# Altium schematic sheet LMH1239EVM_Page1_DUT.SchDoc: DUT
size 431 x 279 mm; Date: Not shown in title block; ApprovedBy: Not shown in title block; CheckedBy: Not shown in title block; Author: Not shown in title block; CompanyName: Not shown in title block; Engineer: Texas Instruments; Organization: Not shown in title block; Address1: Not shown in title block; Address2: Not shown in title block; Address3: Not shown in title block; Address4: Not shown in title block; DocumentNumber: 1; Revision: A; SheetNumber: 1; SheetTotal: 4; PageSetup: Record=PageOptions¦CenterHorizontal=True¦CenterVertical=True¦PrintScale=0.64¦XCorrection=1.00¦YCorrection=1.00¦PrintKind=0¦BorderSize=5000000¦LeftOffset=0¦BottomOffset=0¦Orientation=2¦PaperLength=1000¦PaperWidth=1000¦Scale=100¦PaperSource=15¦PrintQuality=600¦MediaType=1¦DitherType=10¦PaperKind=Letter¦PrintScaleMode=1
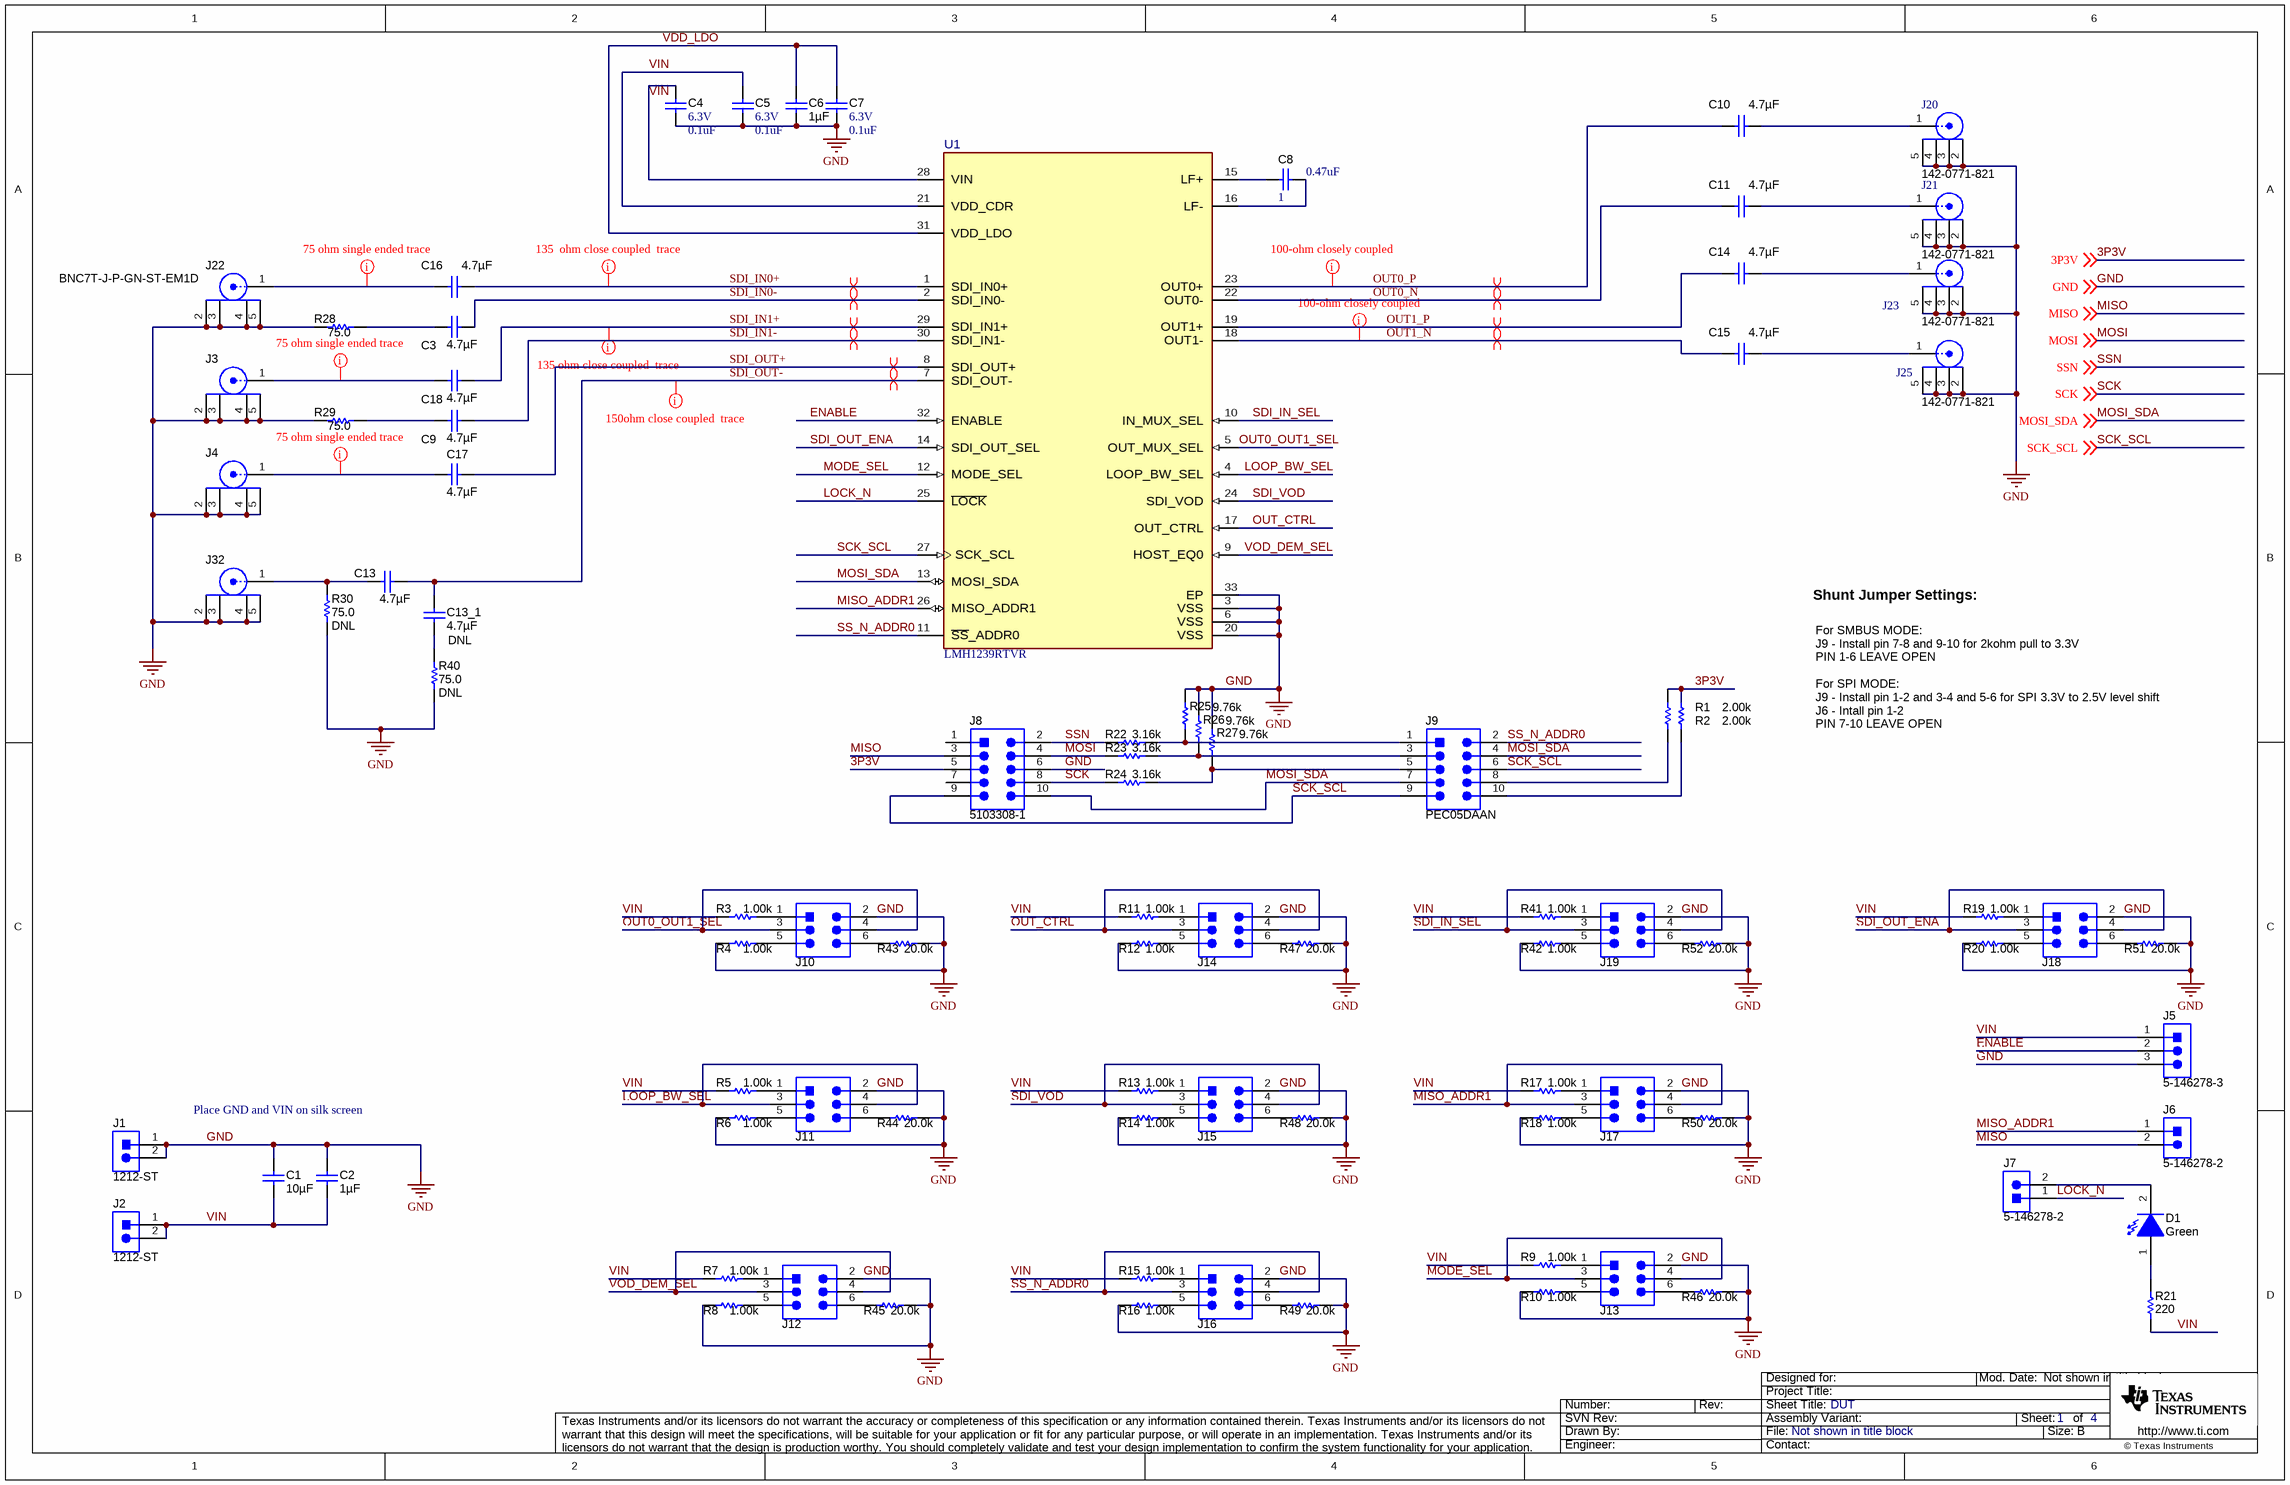
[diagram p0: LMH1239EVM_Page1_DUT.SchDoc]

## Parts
C1  ValueDisplayed: 10µF  [0805_HV]  (hidden comment: 0805YD106MAT2A)
C2  ValueDisplayed: 1µF  [0805_HV]  (hidden comment: 0805YD105KAT2A)
C3  ValueDisplayed: 4.7µF  [0402]  (hidden comment: C1005X5R1A475K050BC)
C4  VDC_V: 6.3V  ValueDisplayed: 0.1uF  [0402]  (hidden comment: C1005X5R0J104K050BA)
C5  VDC_V: 6.3V  ValueDisplayed: 0.1uF  [0402]  (hidden comment: C1005X5R0J104K050BA)
C6  ValueDisplayed: 1µF  [0402]  (hidden comment: C1005X5R0J105M)
C7  VDC_V: 6.3V  ValueDisplayed: 0.1uF  [0402]  (hidden comment: C1005X5R0J104K050BA)
C8  VDC_V: 1  ValueDisplayed: 0.47uF  [0201]  (hidden comment: EMK063BBJ474KPLF)
C9  ValueDisplayed: 4.7µF  [0402]  (hidden comment: C1005X5R1A475K050BC)
C10  ValueDisplayed: 4.7µF  [0402]  (hidden comment: C1005X5R1A475K050BC)
C11  ValueDisplayed: 4.7µF  [0402]  (hidden comment: C1005X5R1A475K050BC)
C13  ValueDisplayed: 4.7µF  [0402]  (hidden comment: C1005X5R1A475K050BC)
C13_1  ValueDisplayed: 4.7µF  Comments: DNL  [0402]  (hidden comment: C1005X5R1A475K050BC)
C14  ValueDisplayed: 4.7µF  [0402]  (hidden comment: C1005X5R1A475K050BC)
C15  ValueDisplayed: 4.7µF  [0402]  (hidden comment: C1005X5R1A475K050BC)
C16  ValueDisplayed: 4.7µF  [0402]  (hidden comment: C1005X5R1A475K050BC)
C17  ValueDisplayed: 4.7µF  [0402]  (hidden comment: C1005X5R1A475K050BC)
C18  ValueDisplayed: 4.7µF  [0402]  (hidden comment: C1005X5R1A475K050BC)
D1  value Green  [LED_SML-LX0603GW]  (hidden comment: SML-LX0603GW-TR)
J1  1212-ST  [Keystone_1212-ST]
J2  1212-ST  [Keystone_1212-ST]
J3  BNC7T-J-P-GN-ST-EM1D  [SAMTEC_BNC7T-J-P-GN-ST-EM1D]
J4  BNC7T-J-P-GN-ST-EM1D  [SAMTEC_BNC7T-J-P-GN-ST-EM1D]  (value not drawn)
J5  5-146278-3  [TE_5-146278-3]
J6  5-146278-2  [TE_5-146278-2]
J7  5-146278-2  [TE_5-146278-2]
J8  5103308-1  [CONN_5103308-1]
J9  PEC05DAAN  [CONN_PEC05DAAN]
J10  5-146254-3  [TE_5-146254-3]  (value not drawn)
J11  5-146254-3  [TE_5-146254-3]  (value not drawn)
J12  5-146254-3  [TE_5-146254-3]  (value not drawn)
J13  5-146254-3  [TE_5-146254-3]  (value not drawn)
J14  5-146254-3  [TE_5-146254-3]  (value not drawn)
J15  5-146254-3  [TE_5-146254-3]  (value not drawn)
J16  5-146254-3  [TE_5-146254-3]  (value not drawn)
J17  5-146254-3  [TE_5-146254-3]  (value not drawn)
J18  5-146254-3  [TE_5-146254-3]  (value not drawn)
J19  5-146254-3  [TE_5-146254-3]  (value not drawn)
J20  142-0771-821  [Emerson_142-0771-821]
J21  142-0771-821  [Emerson_142-0771-821]
J22  (no value)  [SAMTEC_BNC7T-J-P-GN-ST-EM1D]
J23  142-0771-821  [Emerson_142-0771-821]
J25  142-0771-821  [Emerson_142-0771-821]
J32  (no value)  [SAMTEC_BNC7T-J-P-GN-ST-EM1D]
R1  value 2.00k  [0402]  (hidden comment: CRCW04022K00FKED)
R2  value 2.00k  [0402]  (hidden comment: CRCW04022K00FKED)
R3  value 1.00k  [0402]  (hidden comment: CRCW04021K00FKED)
R4  value 1.00k  [0402]  (hidden comment: CRCW04021K00FKED)
R5  value 1.00k  [0402]  (hidden comment: CRCW04021K00FKED)
R6  value 1.00k  [0402]  (hidden comment: CRCW04021K00FKED)
R7  value 1.00k  [0402]  (hidden comment: CRCW04021K00FKED)
R8  value 1.00k  [0402]  (hidden comment: CRCW04021K00FKED)
R9  value 1.00k  [0402]  (hidden comment: CRCW04021K00FKED)
R10  value 1.00k  [0402]  (hidden comment: CRCW04021K00FKED)
R11  value 1.00k  [0402]  (hidden comment: CRCW04021K00FKED)
R12  value 1.00k  [0402]  (hidden comment: CRCW04021K00FKED)
R13  value 1.00k  [0402]  (hidden comment: CRCW04021K00FKED)
R14  value 1.00k  [0402]  (hidden comment: CRCW04021K00FKED)
R15  value 1.00k  [0402]  (hidden comment: CRCW04021K00FKED)
R16  value 1.00k  [0402]  (hidden comment: CRCW04021K00FKED)
R17  value 1.00k  [0402]  (hidden comment: CRCW04021K00FKED)
R18  value 1.00k  [0402]  (hidden comment: CRCW04021K00FKED)
R19  value 1.00k  [0402]  (hidden comment: CRCW04021K00FKED)
R20  value 1.00k  [0402]  (hidden comment: CRCW04021K00FKED)
R21  value 220  [0402]  (hidden comment: CRCW0402220RJNED)
R22  value 3.16k  [0402]  (hidden comment: CRCW04023K16FKED)
R23  value 3.16k  [0402]  (hidden comment: CRCW04023K16FKED)
R24  value 3.16k  [0402]  (hidden comment: CRCW04023K16FKED)
R25  value 9.76k  [0402]  (hidden comment: CRCW04029K76FKED)
R26  value 9.76k  [0402]  (hidden comment: CRCW04029K76FKED)
R27  value 9.76k  [0402]  (hidden comment: CRCW04029K76FKED)
R28  value 75.0  [0402]  (hidden comment: ERJ-PA2F75R0X)
R29  value 75.0  [0402]  (hidden comment: ERJ-PA2F75R0X)
R30  value 75.0  Comments: DNL  [0402]  (hidden comment: ERJ-PA2F75R0X)
R40  value 75.0  Comments: DNL  [0402]  (hidden comment: ERJ-PA2F75R0X)
R41  value 1.00k  [0402]  (hidden comment: CRCW04021K00FKED)
R42  value 1.00k  [0402]  (hidden comment: CRCW04021K00FKED)
R43  value 20.0k  [0402]  (hidden comment: CRCW040220K0FKED)
R44  value 20.0k  [0402]  (hidden comment: CRCW040220K0FKED)
R45  value 20.0k  [0402]  (hidden comment: CRCW040220K0FKED)
R46  value 20.0k  [0402]  (hidden comment: CRCW040220K0FKED)
R47  value 20.0k  [0402]  (hidden comment: CRCW040220K0FKED)
R48  value 20.0k  [0402]  (hidden comment: CRCW040220K0FKED)
R49  value 20.0k  [0402]  (hidden comment: CRCW040220K0FKED)
R50  value 20.0k  [0402]  (hidden comment: CRCW040220K0FKED)
R51  value 20.0k  [0402]  (hidden comment: CRCW040220K0FKED)
R52  value 20.0k  [0402]  (hidden comment: CRCW040220K0FKED)
U1  LMH1239RTVR  [RTV0032E-MFG]

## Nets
GND: C1.1 C2.1 C4.2 C5.2 C6.2 C7.2 J1.1 J1.2 J3.2 J3.3 J3.4 J3.5 J4.2 J4.3 J4.4 J4.5 J5.3 J8.6 J10.2 J11.2 J12.2 J13.2 J14.2 J15.2 J16.2 J17.2 J18.2 J19.2 J20.2 J20.3 J20.4 J20.5 J21.2 J21.3 J21.4 J21.5 J22.2 J22.3 J22.4 J22.5 J23.2 J23.3 J23.4 J23.5 J25.2 J25.3 J25.4 J25.5 J32.2 J32.3 J32.4 J32.5 R4.1 R6.1 R8.1 R10.1 R12.1 R14.1 R16.1 R18.1 R20.1 R25.2 R26.2 R27.2 R28.1 R29.1 R30.1 R40.1 R42.1 R43.2 R44.2 R45.2 R46.2 R47.2 R48.2 R49.2 R50.2 R51.2 R52.2 U1.3(VSS) U1.6(VSS) U1.20(VSS) U1.33(EP) ; off-sheet GND
3P3V: J8.5 R1.2 R2.2 ; off-sheet 3P3V
ENABLE: J5.2 U1.32(ENABLE)
LOCK_N: J7.1 U1.25(~{LOCK})
LOOP_BW_SEL: J11.3 J11.4 U1.4(LOOP_BW_SEL)
MISO: J6.2 J8.3 ; off-sheet MISO
MISO_ADDR1: J6.1 J17.3 J17.4 U1.26(MISO_ADDR1)
MODE_SEL: J13.3 J13.4 U1.12(MODE_SEL)
MOSI: J8.4 R23.1 ; off-sheet MOSI
MOSI_SDA: J8.10 J9.4 J9.7 U1.13(MOSI_SDA) ; off-sheet MOSI_SDA
OUT0_N: C11.2 U1.22(OUT0-)
OUT0_OUT1_SEL: J10.3 J10.4 U1.5(OUT_MUX_SEL)
OUT0_P: C10.2 U1.23(OUT0+)
OUT1_N: C15.2 U1.18(OUT1-)
OUT1_P: C14.2 U1.19(OUT1+)
OUT_CTRL: J14.3 J14.4 U1.17(OUT_CTRL)
SCK: J8.8 R24.1 ; off-sheet SCK
SCK_SCL: J8.9 J9.6 J9.9 U1.27(SCK_SCL) ; off-sheet SCK_SCL
SDI_IN0+: C16.1 U1.1(SDI_IN0+)
SDI_IN0-: C3.1 U1.2(SDI_IN0-)
SDI_IN1+: C18.1 U1.29(SDI_IN1+)
SDI_IN1-: C9.1 U1.30(SDI_IN1-)
SDI_IN_SEL: J19.3 J19.4 U1.10(IN_MUX_SEL)
SDI_OUT+: C17.1 U1.8(SDI_OUT+)
SDI_OUT-: C13.1 C13_1.1 U1.7(SDI_OUT-)
SDI_OUT_ENA: J18.3 J18.4 U1.14(SDI_OUT_SEL)
SDI_VOD: J15.3 J15.4 U1.24(SDI_VOD)
SS_N_ADDR0: J9.2 J16.3 J16.4 U1.11(~{SS}_ADDR0)
SSN: J8.2 R22.1 ; off-sheet SSN
VDD_LDO: C6.1 C7.1 U1.31(VDD_LDO)
VIN: C1.2 C2.2 C4.1 C5.1 J2.1 J2.2 J5.1 R3.1 R5.1 R7.1 R9.1 R11.1 R13.1 R15.1 R17.1 R19.1 R21.1 R41.1 U1.21(VDD_CDR) U1.28(VIN)
VOD_DEM_SEL: J12.3 J12.4 U1.9(HOST_EQ0)
NetC3_2: C3.2 R28.2
NetC8_1: C8.1 U1.15(LF+)
NetC8_2: C8.2 U1.16(LF-)
NetC9_2: C9.2 R29.2
NetC10_1: C10.1 J20.1
NetC11_1: C11.1 J21.1
NetC13_1_2: C13_1.2 R40.2
NetC13_2: C13.2 J32.1 R30.2
NetC14_1: C14.1 J23.1
NetC15_1: C15.1 J25.1
NetC16_2: C16.2 J22.1
NetC17_2: C17.2 J4.1
NetC18_2: C18.2 J3.1
NetD1_1: D1.1(A) R21.2
NetD1_2: D1.2(K) J7.2
NetJ9_1: J9.1 R22.2 R25.1
NetJ9_3: J9.3 R23.2 R26.1
NetJ9_5: J9.5 R24.2 R27.1
NetJ9_8: J9.8 R1.1
NetJ9_10: J9.10 R2.1
NetJ10_1: J10.1 R3.2
NetJ10_5: J10.5 R4.2
NetJ10_6: J10.6 R43.1
NetJ11_1: J11.1 R5.2
NetJ11_5: J11.5 R6.2
NetJ11_6: J11.6 R44.1
NetJ12_1: J12.1 R7.2
NetJ12_5: J12.5 R8.2
NetJ12_6: J12.6 R45.1
NetJ13_1: J13.1 R9.2
NetJ13_5: J13.5 R10.2
NetJ13_6: J13.6 R46.1
NetJ14_1: J14.1 R11.2
NetJ14_5: J14.5 R12.2
NetJ14_6: J14.6 R47.1
NetJ15_1: J15.1 R13.2
NetJ15_5: J15.5 R14.2
NetJ15_6: J15.6 R48.1
NetJ16_1: J16.1 R15.2
NetJ16_5: J16.5 R16.2
NetJ16_6: J16.6 R49.1
NetJ17_1: J17.1 R17.2
NetJ17_5: J17.5 R18.2
NetJ17_6: J17.6 R50.1
NetJ18_1: J18.1 R19.2
NetJ18_5: J18.5 R20.2
NetJ18_6: J18.6 R51.1
NetJ19_1: J19.1 R41.2
NetJ19_5: J19.5 R42.2
NetJ19_6: J19.6 R52.1

Not connected (* = marked no-connect by the designer): J8 1* 7*

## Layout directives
rule Undefined: NetC16_2, NetC17_2, NetC18_2, OUT0_P, OUT1_N, SDI_IN0+, SDI_IN1+, SDI_OUT-
differential pair: OUT0_N, OUT0_P, OUT1_N, OUT1_P, SDI_IN0+, SDI_IN0-, SDI_IN1+, SDI_IN1-, SDI_OUT+, SDI_OUT-

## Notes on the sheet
- Shunt Jumper Settings:
- For SMBUS MODE:
  J9 - Install pin 7-8 and 9-10 for 2kohm pull to 3.3V
  PIN 1-6 LEAVE OPEN
  For SPI MODE:
  J9 - Install pin 1-2 and 3-4 and 5-6 for SPI 3.3V to 2.5V level shift
  J6 - Intall pin 1-2
  PIN 7-10 LEAVE OPEN
- Place GND and VIN on silk screen

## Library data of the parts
C1 = 0805YD106MAT2A: CAP, CERM, 10uF, 16V, +/-20%, X5R, 0805; Manufacturer: AVX; Polarized: N; CompType: Capacitor; U/M: EA; Cap_F: 0.00001; Tolerance_%: 20; Value1: Unknown; VDC_V: 16; TaMin_C: -55; TaMax_C: 85; Cap_Case: 0805
C2 = 0805YD105KAT2A: CAP, CERM, 1uF, 16V, +/-10%, X5R, 0805; Manufacturer: AVX; Polarized: N; CompType: Capacitor; U/M: EA; Cap_F: 0.000001; Tolerance_%: 10; ESR_Ohm: 0.012; Value1: 0.012 ohm; VDC_V: 16; TaMin_C: -55; TaMax_C: 85; Cap_Case: 0805
C3 C9-C11 C13 C13_1 C14-C18 = C1005X5R1A475K050BC: CAP, CERM, 4.7 µF, 10 V, +/- 10%, X5R, 0402; Manufacturer: TDK; Polarized: N; CompType: Capacitor; Value: 4.7uF; U/M: EA; Cap_F: 0.0000047; Tolerance_%: 10; Value1: Unknown; Value2: 10V; TaMin_C: -55; TaMax_C: 85
C4 C5 C7 = CMP-0006255-1: CAP, CERM, 0.1 uF, 6.3 V, +/- 10%, X5R, 0402; Manufacturer: TDK; TaMin_C: -55°C; ESR_ohm: 18.6m; Polarized: N; SizeAreaWB_mm2: 3; Value1: 0.0186 ohm; U/M: EA; Value: 0.1uF; TaMax_C: 85°C; SizeZ_mm: 0.6; SizeX_mm: 1; SizeY_mm: 0.5; Cap_F: 100nF; AEC Category: Q200
C6 = C1005X5R0J105M: CAP, CERM, 1 µF, 6.3 V, +/- 20%, X5R, 0402; Manufacturer: TDK; Polarized: N; CompType: Capacitor; Value: 1uF; U/M: EA; Cap_F: 0.000001; Tolerance_%: 20; ESR_ohm: 0.0079; Value1: 0.0079 ohm; VDC_V: 6.3; Value2: 6.3V; TaMin_C: -55; TaMax_C: 85; AEC Category: Q200
C8 = CMP-0008868-2: CAP CER 0.47UF 16V X5R 0201; Manufacturer: Taiyo Yuden; TaMin_C: -55°C; Polarized: N; TempCo: X7R; SizeAreaWB_mm2: 10.92; Value1: Unknown; U/M: EA; TaMax_C: 125°C; Tolerance_%: 10%; SizeZ_mm: 1.35; SizeX_mm: 3.2; SizeY_mm: 1.6; SizeArea_mm2: 5.12; Cap_F: 470nF; AEC Category: Q200
D1 = SML-LX0603GW-TR: LED, Green, SMD; Manufacturer: Lumex; Vf_V: 2.2; Value2: 2.2V; Io_A: 0.02; Tjmax_C: 85; Value1: W; U/M: EA
J1 J2 = 1212-ST: Disconnect Terminal, 5.08mm, 2x1, Tin, TH; Manufacturer: Keystone; SymbolCreator: a0412235; U/M: EA
J3 J4 J22 J32 = BNC7T-J-P-GN-ST-EM1D: Connector, BNC Edge Mount, SMD; Manufacturer: Samtec; SymbolCreator: Altium; U/M: EA
J5 = 5-146278-3: Header, 100mil, 3x1, Tin, TH; Manufacturer: TE Connectivity; SymbolCreator: a0799628
J6 J7 = 5-146278-2: Header, 100mil, 2x1, Tin, TH; Manufacturer: TE Connectivity; SymbolCreator: a0412235; U/M: EA
J8 = 5103308-1: Header (shrouded), 100mil, 5x2, Gold, TH; Manufacturer: TE Connectivity; SymbolCreator: a0412235; U/M: EA
J9 = PEC05DAAN: Header, 100mil, 5x2, Tin, TH; Manufacturer: Sullins Connector Solutions; SymbolCreator: a0412235; U/M: EA
J10-J19 = 5-146254-3: Header, 100mil, 3x2, Tin, TH; Manufacturer: TE Connectivity; SymbolCreator: a0412235; U/M: EA
J20 J21 J23 J25 = CMP-0055824-1: Connector, End launch SMA 50 ohm, TH; Manufacturer: Cinch Connectivity; CNHeader: FALSE; Green_Lifecycle: Not Set; Green_REACh: Incomplete; CT: TRUE
R1 R2 = CRCW04022K00FKED: RES, 2.00k ohm, 1%, 0.063W, 0402; Manufacturer: Vishay-Dale; CompType: Resistor; Res_ohm: 2000; Value_Code: 2k00; Tolerance_%: 1; Power_W: 0.063; VDC_V: 50; TempCo: 100 ppm/C; EIA_Code: E96; U/M: EA
R3-R20 R41 R42 = CRCW04021K00FKED: RES, 1.00k ohm, 1%, 0.063W, 0402; Manufacturer: Vishay-Dale; CompType: Resistor; Res_ohm: 1000; Value_Code: 1k00; Tolerance_%: 1; Power_W: 0.063; VDC_V: 50; TempCo: 100 ppm/C; EIA_Code: E96; U/M: EA
R21 = CRCW0402220RJNED: RES, 220 ohm, 5%, 0.063W, 0402; Manufacturer: Vishay-Dale; CompType: Resistor; Value_Code: 220R; Tolerance_%: 5; Power_W: 0.063; VDC_V: 50; TempCo: 200 ppm/C; EIA_Code: E24; U/M: EA
R22-R24 = CRCW04023K16FKED: RES, 3.16k ohm, 1%, 0.063W, 0402; Manufacturer: Vishay-Dale; CompType: Resistor; Res_ohm: 3160; Value_Code: 3k16; Tolerance_%: 1; Power_W: 0.063; VDC_V: 50; TempCo: 100 ppm/C; EIA_Code: E96; U/M: EA
R25-R27 = CRCW04029K76FKED: RES, 9.76k ohm, 1%, 0.063W, 0402; Manufacturer: Vishay-Dale; CompType: Resistor; Res_ohm: 9760; Value_Code: 9k76; Tolerance_%: 1; Power_W: 0.063; VDC_V: 50; TempCo: 100 ppm/C; EIA_Code: E96; U/M: EA
R28-R30 R40 = CRCW04023K16FKED: RES SMD 75 OHM 1% 1/5W 0402; Manufacturer: Panasonic Electronic Components; CompType: Resistor; Res_ohm: 3160; Value_Code: 75; Tolerance_%: 1; Power_W: 0.063; Value2: 0.2W; VDC_V: 50; TempCo: 100 ppm/C; EIA_Code: E96; U/M: EA
R43-R52 = CRCW040220K0FKED: RES, 20.0k ohm, 1%, 0.063W, 0402; Manufacturer: Vishay-Dale; CompType: Resistor; Res_ohm: 20000; Value_Code: 20k0; Tolerance_%: 1; Power_W: 0.063; VDC_V: 50; TempCo: 100 ppm/C; EIA_Code: E96; U/M: EA
U1 = CMP-0094574-1: 12G UHD-SDI Long Reach Adaptive Cable Equalizer with Integrated Reclocker Product Requirement Specifications (PRS), WQFN32; Manufacturer: Texas Instruments; Max Supply Voltage: 2.625V; Standoff Height: 0mm; SizeZ_mm: 0.8mm; Min Supply Voltage: 2.375V; Interface: SPI,SMBus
